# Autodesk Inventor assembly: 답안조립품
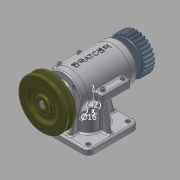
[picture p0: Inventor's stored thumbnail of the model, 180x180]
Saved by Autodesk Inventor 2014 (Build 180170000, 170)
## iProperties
Created: 2015-07
Part Number: 답안조립품
Document SubType Name: Assembly
Designer: study
Mass: 2346.09 g
Surface Area: 1568.58 cm^2
Volume: 520.706 cm^3
Density: 4.5056 g/cm^3
Author: study
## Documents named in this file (18)
- C:\Users\study\Desktop\350705V1027\답안조립품.iam
- C:\Users\study\Desktop\350705V1027\본체.ipt
- C:\Users\study\Desktop\350705V1027\본체 커버.ipt
- C:\Users\study\Desktop\350705V1027\뒤커버.ipt
- C:\Users\study\Desktop\350705V1027\앞커버.ipt
- C:\Users\study\Desktop\350705V1027\베어링 6201.ipt
- C:\Users\study\Desktop\350705V1027\베어링 6202.ipt
- C:\Users\study\Desktop\350705V1027\오일실.ipt
- C:\Users\study\Desktop\350705V1027\M3x0.5x8.ipt
- C:\Users\study\Desktop\350705V1027\M4x20.ipt
- C:\Users\study\Desktop\350705V1027\편심축.ipt
- C:\Users\study\Desktop\350705V1027\키4x4.ipt
- C:\Users\study\Desktop\350705V1027\키5x5.ipt
- C:\Users\study\Desktop\350705V1027\V-벨트풀리.ipt
- C:\Users\study\Desktop\350705V1027\멈춤나사.ipt
- C:\Users\study\Desktop\350705V1027\메인기어.ipt
- C:\Users\study\Desktop\350705V1027\슬라이드.ipt
- C:\Users\study\Desktop\350705V1027\가변스프링.ipt
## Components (14 placed, 4 different names)
1. M4x0.5x14:1
2. M4x0.5x14:2
3. M4x0.5x14:3
4. M4x0.5x14:4
5. M3x0.5x8:1
6. M3x0.5x8:2
7. M3x0.5x8:3
8. M3x0.5x8:4
9. M3x0.5x8:5
10. M3x0.5x8:6
11. M3x0.5x8:7
12. M3x0.5x8:8
13. V-벨트풀리:1 — 플러쉬:1
14. 가변스프링:1
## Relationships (1: Flush 1)
- 플러쉬:1 [Flush]: V-벨트풀리:1
